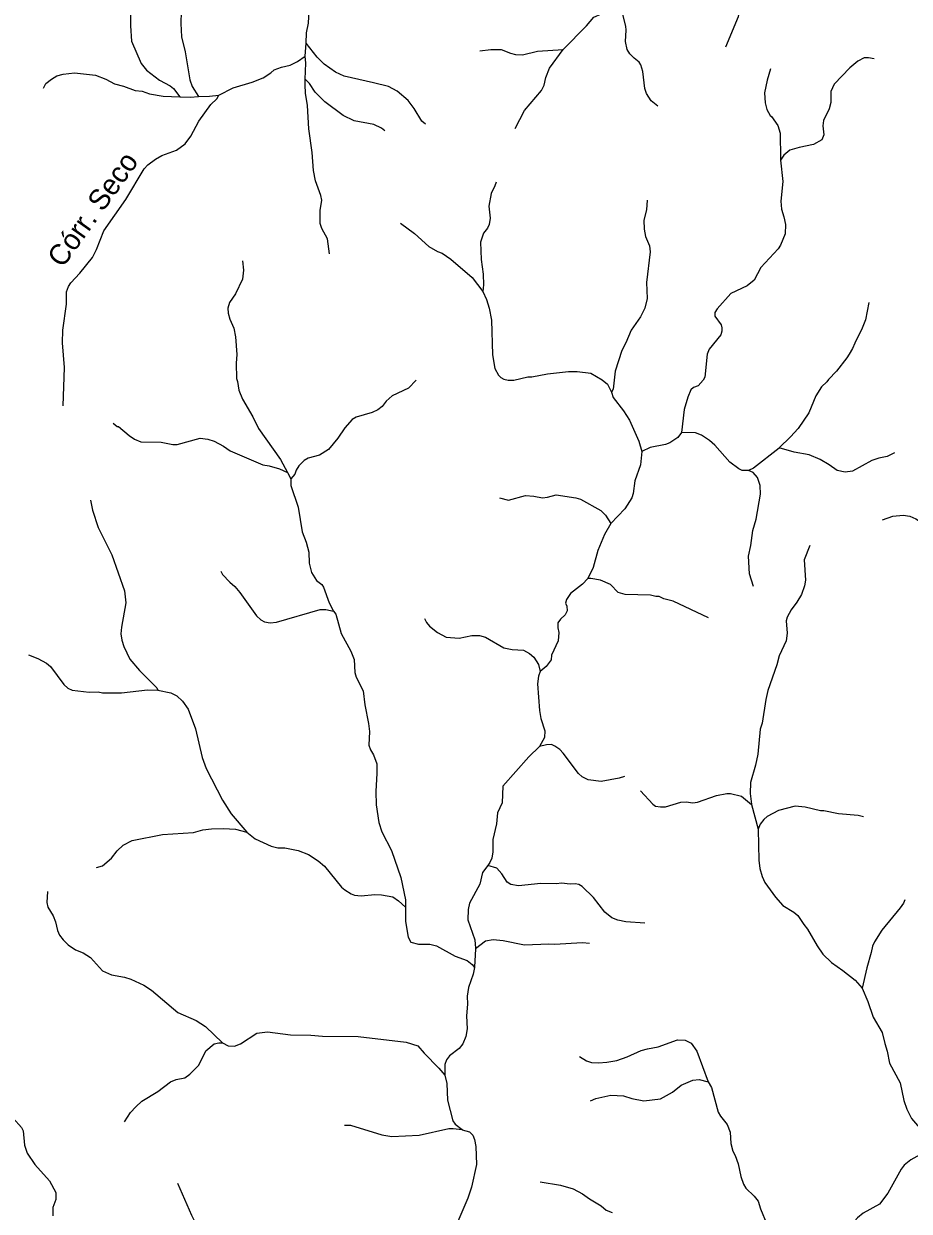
# Model space of a CAD drawing. Extents: x 500 to 555.2, y 9115.7 to 9171.
# Drawn here: x 506.57 to 513.43, y 9152.3 to 9161.51 of the extents above; entities that cross this region are included whole.
import ezdxf
from ezdxf.enums import TextEntityAlignment as Align

# ---------------------------------------------------------------- set-up
doc = ezdxf.new("R2010")
doc.units = 0
doc.header["$LTSCALE"] = 0.064
doc.layers.add('61', color=7, linetype='Continuous')
doc.layers.add('7', color=7, linetype='Continuous', lineweight=25)

msp = doc.modelspace()

# ---------------------------------------------------------------- linework, layer by layer
at = {"layer": '7'}
for p, q in [((508.747, 9161.2588), (508.7554, 9161.3589)), ((508.6097, 9158.0285), (508.6356, 9157.9796)), ((512.2057, 9155.4545), (512.2566, 9155.2643)), ((509.8286, 9153.3552), (509.8445, 9153.2913))]:
    msp.add_line(p, q, dxfattribs=at)
for points in [[(512.0079, 9161.3296), (512.1062, 9161.5663), (512.126, 9161.6638), (512.1276, 9161.7213), (512.1381, 9161.7481), (512.1532, 9161.7679), (512.1793, 9161.7797), (512.1942, 9161.7833), (512.2145, 9161.7826), (512.2757, 9161.753), (512.3157, 9161.743), (512.3493, 9161.7422), (512.3718, 9161.7497), (512.4665, 9161.8121), (512.5762, 9161.8589), (512.6381, 9161.8973), (512.6862, 9161.9426), (512.7107, 9162.0084), (512.7249, 9162.0852), (512.7809, 9162.164), (512.783, 9162.1652)], [(508.7554, 9161.3589), (508.757, 9161.4388), (508.773, 9161.5128), (508.7789, 9161.6115), (508.811, 9161.74), (508.8226, 9161.8187), (508.8257, 9161.8802)], [(507.3953, 9161.7929), (507.3925, 9161.4936), (507.4008, 9161.3752), (507.4757, 9161.2012), (507.5161, 9161.1489), (507.6167, 9161.0714), (507.7005, 9161.0283), (507.7258, 9161.0061), (507.776, 9160.9435)], [(507.7474, 9161.7496), (507.7531, 9161.7242), (507.7665, 9161.702), (507.7861, 9161.6036), (507.7828, 9161.51), (507.7879, 9161.4067), (507.8172, 9161.2919), (507.8535, 9161.0755), (507.8716, 9161.023), (507.9189, 9160.9438)], [(510.747, 9161.3091), (510.9278, 9161.4926), (510.985, 9161.5609), (511.1032, 9161.6127), (511.1848, 9161.6706)], [(511.4812, 9160.87), (511.4289, 9160.9118), (511.3927, 9160.9683), (511.3782, 9161.0083), (511.3652, 9161.1383), (511.3475, 9161.1897), (511.3353, 9161.2116), (511.2969, 9161.2423), (511.2628, 9161.2764), (511.2427, 9161.3105), (511.2292, 9161.3714), (511.2355, 9161.4593), (511.2323, 9161.4895), (511.1848, 9161.6706)], [(509.6788, 9160.7296), (509.6514, 9160.7542), (509.5905, 9160.8523), (509.5442, 9160.9147), (509.4587, 9160.9856), (509.3915, 9161.0215), (509.276, 9161.0511), (509.0482, 9161.1017), (508.9831, 9161.1338), (508.8938, 9161.1963), (508.8405, 9161.2506), (508.7554, 9161.3589)], [(510.0994, 9161.2982), (510.1853, 9161.3083), (510.267, 9161.31), (510.3381, 9161.2802), (510.3775, 9161.2705), (510.4319, 9161.269), (510.5469, 9161.2968), (510.747, 9161.3091)], [(510.3747, 9160.6963), (510.4469, 9160.8354), (510.5787, 9160.9906), (510.5989, 9161.0323), (510.6125, 9161.0924), (510.6407, 9161.1639), (510.7468, 9161.3089), (510.747, 9161.3091)], [(508.0787, 9160.9562), (508.188, 9161.0114), (508.3351, 9161.0555), (508.4218, 9161.0907), (508.48, 9161.128), (508.5069, 9161.1519), (508.5627, 9161.1724), (508.6303, 9161.1881), (508.6862, 9161.2161), (508.747, 9161.2588)], [(508.7475, 9161.0796), (508.7522, 9161.2045), (508.747, 9161.2588)], [(513.1563, 9161.2363), (513.1135, 9161.2459), (513.0801, 9161.2444), (513.0314, 9161.2188), (512.969, 9161.1685), (512.8468, 9161.0414), (512.8205, 9160.9842), (512.8202, 9160.8983), (512.8087, 9160.8492), (512.7648, 9160.7578), (512.758, 9160.7174), (512.766, 9160.6484), (512.751, 9160.608), (512.6878, 9160.5721), (512.5762, 9160.5502), (512.5041, 9160.5277), (512.4562, 9160.4913), (512.4312, 9160.4524)], [(506.7188, 9161.0104), (506.738, 9161.0453), (506.7796, 9161.0793), (506.8234, 9161.1049), (506.8713, 9161.1195), (506.9582, 9161.128), (507.1218, 9161.1098), (507.2027, 9161.0792), (507.2684, 9161.0433), (507.3378, 9161.0263), (507.4283, 9160.9924), (507.4832, 9160.9861), (507.5408, 9160.967), (507.6467, 9160.9475), (507.776, 9160.9435)], [(508.9353, 9159.7257), (508.9195, 9159.8403), (508.8751, 9159.9212), (508.8622, 9159.9606), (508.864, 9160.0623), (508.8753, 9160.1416), (508.8683, 9160.1774), (508.8276, 9160.292), (508.8115, 9160.3704), (508.8, 9160.5106), (508.7754, 9160.6936), (508.764, 9160.8763), (508.7491, 9160.9711), (508.7458, 9161.0354), (508.7475, 9161.0796)], [(509.3647, 9160.6801), (509.3387, 9160.6991), (509.2784, 9160.7289), (509.1277, 9160.7561), (509.0421, 9160.7986), (508.9002, 9160.9046), (508.8237, 9160.9794), (508.7792, 9161.0465), (508.7475, 9161.0796)], [(512.3546, 9161.1597), (512.3271, 9161.0709), (512.3072, 9160.9724), (512.3132, 9160.8968), (512.3258, 9160.844), (512.3498, 9160.7979), (512.3611, 9160.791), (512.4103, 9160.7206), (512.428, 9160.6601), (512.43, 9160.4632), (512.4312, 9160.4524)], [(506.8709, 9158.5462), (506.8808, 9158.8446), (506.866, 9159.0349), (506.8677, 9159.1339), (506.8971, 9159.3341), (506.897, 9159.4305), (506.9119, 9159.4712), (506.93, 9159.4991), (507.0008, 9159.575), (507.0988, 9159.696), (507.1298, 9159.7578), (507.1856, 9159.9021), (507.3577, 9160.1467), (507.4979, 9160.3836), (507.5265, 9160.4142), (507.5858, 9160.4592), (507.6348, 9160.487), (507.7484, 9160.5293), (507.8165, 9160.5778), (507.8609, 9160.6382), (507.923, 9160.7534), (508.015, 9160.8827), (508.0614, 9160.9259), (508.0787, 9160.9562)], [(507.776, 9160.9435), (507.8554, 9160.941), (507.9189, 9160.9438)], [(507.9189, 9160.9438), (508.0051, 9160.9476), (508.0777, 9160.9557), (508.0787, 9160.9562)], [(512.4312, 9160.4524), (512.4496, 9160.2849), (512.4333, 9160.1324), (512.4397, 9160.0716), (512.4577, 9160.0125), (512.4685, 9159.9514), (512.4673, 9159.8809), (512.4313, 9159.7928), (512.4127, 9159.7645), (512.2783, 9159.6201), (512.2279, 9159.5206), (512.1713, 9159.4781), (512.0472, 9159.4163), (511.94, 9159.2995), (511.9225, 9159.2702), (511.9218, 9159.2429), (511.9704, 9159.175), (511.9763, 9159.1504), (511.9763, 9159.1247), (511.9686, 9159.0965), (511.8781, 9158.9854), (511.8626, 9158.9468), (511.8443, 9158.7699), (511.8317, 9158.7456), (511.7938, 9158.7024), (511.7579, 9158.6889), (511.7351, 9158.6696), (511.7119, 9158.6131), (511.6854, 9158.5181), (511.6647, 9158.3397)], [(510.2261, 9160.2811), (510.2177, 9160.2518), (510.1877, 9160.1929), (510.1712, 9160.094), (510.1809, 9160.0016), (510.1733, 9159.952), (510.1606, 9159.9229), (510.1303, 9159.8861), (510.1065, 9159.8143), (510.1121, 9159.6819), (510.1268, 9159.567), (510.1299, 9159.4844), (510.1231, 9159.4331)], [(511.398, 9160.14), (511.3913, 9160.0671), (511.372, 9159.9869), (511.3735, 9159.9161), (511.3848, 9159.8589), (511.4158, 9159.7873), (511.4211, 9159.7411), (511.3932, 9159.502), (511.3965, 9159.3776), (511.3798, 9159.3034), (511.3462, 9159.2366), (511.2729, 9159.1321), (511.2321, 9159.0344), (511.2011, 9158.9753), (511.1505, 9158.8151), (511.1339, 9158.6766), (511.1199, 9158.6532)], [(509.4847, 9159.9635), (509.5954, 9159.8829), (509.7054, 9159.7829), (509.7737, 9159.7429), (509.8081, 9159.7304), (509.8754, 9159.6831), (510.0408, 9159.5409), (510.1231, 9159.4331)], [(508.2611, 9159.6706), (508.2684, 9159.5992), (508.2613, 9159.529), (508.208, 9159.416), (508.1603, 9159.3465), (508.1487, 9159.3039), (508.1503, 9159.2651), (508.1617, 9159.2192), (508.1947, 9159.1491), (508.2062, 9159.0802), (508.2175, 9158.9437), (508.2111, 9158.8781), (508.2143, 9158.7574), (508.2224, 9158.7355), (508.2324, 9158.6676), (508.2619, 9158.5969), (508.3419, 9158.4614), (508.3856, 9158.371), (508.5554, 9158.1311), (508.6097, 9158.0285)], [(510.1231, 9159.4331), (510.1513, 9159.3707), (510.1728, 9159.3033), (510.1923, 9159.2095), (510.1991, 9158.9424), (510.2168, 9158.8364), (510.2458, 9158.7853), (510.2637, 9158.7653), (510.2866, 9158.7526), (510.3189, 9158.7449), (510.3642, 9158.7446), (510.4732, 9158.7705), (510.5041, 9158.7709), (510.6255, 9158.7938), (510.788, 9158.8117), (510.8545, 9158.8134), (510.9614, 9158.7996), (511.0482, 9158.7482), (511.0894, 9158.7133), (511.1199, 9158.6532)], [(513.1147, 9159.3485), (513.0886, 9159.2135), (513.0638, 9159.148), (513.0069, 9159.0325), (512.9886, 9158.9904), (512.9633, 9158.9478), (512.9441, 9158.9192), (512.865, 9158.8153), (512.8019, 9158.7505), (512.7909, 9158.7319), (512.7495, 9158.6949), (512.7051, 9158.6242), (512.6499, 9158.4925), (512.5672, 9158.3702), (512.5092, 9158.3056), (512.4218, 9158.2211)], [(509.6071, 9158.7451), (509.5482, 9158.6826), (509.4206, 9158.6241), (509.3734, 9158.5817), (509.3439, 9158.5424), (509.3092, 9158.515), (509.2673, 9158.4953), (509.1421, 9158.4578), (509.1118, 9158.4401), (509.0535, 9158.3747), (509.0003, 9158.2951), (508.927, 9158.2074), (508.8583, 9158.1644), (508.7702, 9158.1414), (508.7393, 9158.1229), (508.6982, 9158.0802), (508.677, 9158.0475), (508.6659, 9158.0157), (508.6356, 9157.9796)], [(511.1199, 9158.6532), (511.133, 9158.6109), (511.2138, 9158.5069), (511.2596, 9158.4359), (511.3336, 9158.272), (511.3564, 9158.1912)], [(507.2579, 9158.4111), (507.2907, 9158.3869), (507.2994, 9158.3864), (507.3822, 9158.3153), (507.4232, 9158.2873), (507.4724, 9158.2659), (507.6309, 9158.2638), (507.7222, 9158.2476), (507.7544, 9158.2476), (507.9334, 9158.295), (507.9933, 9158.2872), (508.042, 9158.2721), (508.1126, 9158.2328), (508.1645, 9158.1962), (508.4189, 9158.0896), (508.4669, 9158.0819), (508.5489, 9158.0589), (508.6097, 9158.0285)], [(511.6647, 9158.3397), (511.6645, 9158.3383), (511.634, 9158.3011), (511.572, 9158.2583), (511.5394, 9158.2456), (511.4213, 9158.2241), (511.3564, 9158.1912)], [(512.1836, 9158.0439), (512.1346, 9158.0455), (512.1074, 9158.0578), (512.0391, 9158.1103), (511.9225, 9158.2415), (511.8803, 9158.2787), (511.8176, 9158.3189), (511.773, 9158.3378), (511.6647, 9158.3397)], [(511.3564, 9158.1912), (511.3451, 9158.0876), (511.3029, 9157.9648), (511.2881, 9157.8671), (511.2775, 9157.8329), (511.2242, 9157.7473), (511.1169, 9157.6334)], [(512.4218, 9158.2211), (512.4196, 9158.219), (512.2207, 9158.0632), (512.1836, 9158.0439)], [(513.3152, 9158.1823), (513.2576, 9158.1546), (513.1927, 9158.1414), (513.14, 9158.1237), (512.9891, 9158.0409), (512.9317, 9158.0311), (512.8696, 9158.046), (512.8092, 9158.0897), (512.739, 9158.1306), (512.6519, 9158.1669), (512.5381, 9158.187), (512.4218, 9158.2211)], [(512.2223, 9157.1443), (512.1901, 9157.2426), (512.1822, 9157.3815), (512.2, 9157.4641), (512.2152, 9157.5795), (512.2412, 9157.667), (512.2756, 9157.861), (512.2721, 9157.9274), (512.2535, 9157.99), (512.2187, 9158.0289), (512.1836, 9158.0439)], [(508.6356, 9157.9796), (508.6367, 9157.9288), (508.6927, 9157.7602), (508.7226, 9157.5692), (508.7539, 9157.4897), (508.775, 9157.4117), (508.7788, 9157.3275), (508.7957, 9157.2532), (508.8349, 9157.1916), (508.8764, 9157.1604), (508.8887, 9157.1398), (508.9325, 9157.018), (508.9675, 9156.9538)], [(510.2532, 9157.8328), (510.3237, 9157.8146), (510.4538, 9157.8505), (510.5194, 9157.8459), (510.5873, 9157.8328), (510.6255, 9157.8375), (510.6935, 9157.8572), (510.8434, 9157.8339), (510.8809, 9157.8213), (511.0372, 9157.734), (511.0749, 9157.6996), (511.1169, 9157.6334)], [(507.0835, 9157.8138), (507.099, 9157.7385), (507.1426, 9157.6017), (507.2481, 9157.3914), (507.3466, 9157.1118), (507.3579, 9157.0199), (507.3222, 9156.8288), (507.3187, 9156.7786), (507.3253, 9156.7287), (507.3414, 9156.6801), (507.3882, 9156.5814), (507.4618, 9156.4938), (507.5966, 9156.3607), (507.6061, 9156.3403)], [(513.2219, 9157.6625), (513.3005, 9157.6901), (513.3818, 9157.6997), (513.4324, 9157.6908), (513.4791, 9157.6704), (513.5297, 9157.639), (513.5786, 9157.6226), (513.6278, 9157.6178), (513.7087, 9157.6308), (513.799, 9157.632), (513.9171, 9157.6058), (514.01, 9157.5689), (514.1363, 9157.5076), (514.279, 9157.4541), (514.4025, 9157.3858), (514.4503, 9157.3506)], [(511.1169, 9157.6334), (511.0667, 9157.5487), (511.0148, 9157.4256), (510.9795, 9157.2923), (510.9384, 9157.207)], [(512.658, 9157.4625), (512.6153, 9157.352), (512.6249, 9157.1951), (512.6182, 9157.1513), (512.5935, 9157.0825), (512.5586, 9157.0228), (512.5132, 9156.9644), (512.4828, 9156.907), (512.4757, 9156.8799), (512.4824, 9156.7834), (512.476, 9156.7235), (512.4202, 9156.6079), (512.4037, 9156.5391), (512.333, 9156.3377), (512.3164, 9156.2681), (512.2885, 9156.0851), (512.2724, 9156.0391), (512.2543, 9155.8463), (512.2373, 9155.7586), (512.1988, 9155.6245), (512.1954, 9155.5401), (512.2051, 9155.4568), (512.2057, 9155.4545)], [(508.0927, 9157.2633), (508.107, 9157.2377), (508.1628, 9157.1789), (508.2015, 9157.1465), (508.2417, 9157.0997), (508.3687, 9156.9171), (508.4034, 9156.8875), (508.4304, 9156.8726), (508.4751, 9156.8633), (508.5249, 9156.8699), (508.8638, 9156.9665), (508.9076, 9156.9681), (508.9675, 9156.9538)], [(510.9384, 9157.207), (510.8959, 9157.1642), (510.8027, 9157.0911), (510.7715, 9157.0452), (510.765, 9157.0162), (510.7746, 9156.9916), (510.7776, 9156.9578), (510.7612, 9156.9268), (510.726, 9156.893), (510.706, 9156.8624), (510.7043, 9156.8245), (510.7123, 9156.7877), (510.7075, 9156.7245), (510.6568, 9156.6121), (510.6545, 9156.5756), (510.6144, 9156.5242), (510.5691, 9156.4859)], [(511.8718, 9156.9011), (511.5994, 9157.0315), (511.5273, 9157.0509), (511.4896, 9157.0677), (511.4653, 9157.0668), (511.4226, 9157.0779), (511.2265, 9157.083), (511.1721, 9157.0995), (511.1127, 9157.1617), (511.0356, 9157.1944), (510.962, 9157.2076), (510.9384, 9157.207)], [(508.9675, 9156.9538), (508.9857, 9156.9315), (509.025, 9156.7797), (509.101, 9156.6448), (509.1277, 9156.5784), (509.1314, 9156.4794), (509.1428, 9156.4433), (509.1967, 9156.335), (509.2081, 9156.2283), (509.238, 9156.0842), (509.2442, 9156.0207), (509.2415, 9155.9147), (509.2543, 9155.8793), (509.2767, 9155.8402), (509.3018, 9155.7701), (509.3034, 9155.6985), (509.2936, 9155.5558), (509.2969, 9155.4525), (509.3184, 9155.3141), (509.3406, 9155.244), (509.4152, 9155.0976), (509.489, 9154.8876), (509.5247, 9154.716), (509.5242, 9154.6587)], [(509.6707, 9156.8974), (509.6865, 9156.8661), (509.7108, 9156.8367), (509.7731, 9156.789), (509.8388, 9156.7515), (509.9412, 9156.7451), (510.0396, 9156.7665), (510.0979, 9156.7662), (510.1439, 9156.7513), (510.2854, 9156.6708), (510.3512, 9156.6563), (510.438, 9156.651), (510.486, 9156.6253), (510.5188, 9156.5973), (510.5545, 9156.5392), (510.5691, 9156.4859)], [(506.6038, 9156.6152), (506.6752, 9156.5878), (506.7413, 9156.5499), (506.7731, 9156.5245), (506.8765, 9156.3853), (506.9086, 9156.358), (506.9401, 9156.3411), (507.072, 9156.3269), (507.1421, 9156.3284), (507.1749, 9156.3219), (507.3233, 9156.3219), (507.5248, 9156.3431), (507.6061, 9156.3403)], [(510.5691, 9156.4859), (510.5544, 9156.4493), (510.5469, 9156.3901), (510.5633, 9156.1835), (510.5738, 9156.1223), (510.604, 9156.0273), (510.6025, 9155.9748), (510.5632, 9155.9035)], [(507.6061, 9156.3403), (507.7052, 9156.3204), (507.7517, 9156.2971), (507.7959, 9156.2562), (507.8402, 9156.1939), (507.8956, 9156.0412), (507.9474, 9155.8185), (507.9787, 9155.7339), (508.1057, 9155.4893), (508.1737, 9155.3831), (508.2946, 9155.2416)], [(511.2225, 9155.6718), (511.1797, 9155.6578), (511.0402, 9155.633), (510.941, 9155.646), (510.895, 9155.6704), (510.8645, 9155.6957), (510.7468, 9155.8527), (510.7206, 9155.8805), (510.6829, 9155.908), (510.6549, 9155.9198), (510.618, 9155.9181), (510.5632, 9155.9035)], [(510.5632, 9155.9035), (510.48, 9155.8253), (510.2781, 9155.5968), (510.2749, 9155.4678), (510.2368, 9155.3897), (510.2307, 9155.3042), (510.2002, 9155.1826), (510.2023, 9155.0872), (510.194, 9155.0393), (510.1788, 9155.0041), (510.1631, 9154.9807)], [(511.3462, 9155.5603), (511.4415, 9155.4566), (511.4616, 9155.4431), (511.5001, 9155.4363), (511.5402, 9155.4377), (511.659, 9155.4738), (511.6989, 9155.4754), (511.752, 9155.469), (511.7868, 9155.4739), (511.9346, 9155.5246), (512.016, 9155.541), (512.0422, 9155.541), (512.1274, 9155.5199), (512.2057, 9155.4545)], [(513.0747, 9155.3592), (513.0316, 9155.3691), (512.8803, 9155.3837), (512.7672, 9155.4049), (512.7415, 9155.405), (512.6229, 9155.4345), (512.5452, 9155.4426), (512.4162, 9155.408), (512.3287, 9155.361), (512.3014, 9155.3387), (512.2739, 9155.3034), (512.2566, 9155.2643)], [(507.1287, 9154.9656), (507.1748, 9154.9805), (507.2465, 9155.0376), (507.2901, 9155.0959), (507.3368, 9155.1392), (507.4061, 9155.1763), (507.6408, 9155.2228), (507.882, 9155.2387), (507.9525, 9155.2575), (508.0202, 9155.2673), (508.1141, 9155.2688), (508.2062, 9155.2623), (508.2946, 9155.2416)], [(508.2946, 9155.2416), (508.3593, 9155.1899), (508.4827, 9155.1313), (508.5358, 9155.1196), (508.5897, 9155.1193), (508.6932, 9155.0982), (508.7733, 9155.0662), (508.8485, 9155.0182), (508.8961, 9154.9773), (509.0295, 9154.8144), (509.0533, 9154.7921), (509.1021, 9154.761), (509.1297, 9154.7522), (509.1806, 9154.7472), (509.2856, 9154.757), (509.3381, 9154.7555), (509.427, 9154.7392), (509.4713, 9154.7089), (509.5242, 9154.6587)], [(512.2566, 9155.2643), (512.2572, 9155.2619), (512.2626, 9155.0221), (512.2709, 9154.9598), (512.2883, 9154.8963), (512.3083, 9154.8496), (512.3914, 9154.7361), (512.4495, 9154.6719), (512.5331, 9154.6208), (512.5642, 9154.593), (512.6107, 9154.5236), (512.6414, 9154.488), (512.7156, 9154.3596), (512.76, 9154.2941), (512.8257, 9154.2301), (512.9148, 9154.1685), (513.0093, 9154.0921), (513.0649, 9154.0301)], [(510.1631, 9154.9807), (510.1219, 9154.9269), (510.1, 9154.8377), (510.0217, 9154.6908), (510.0102, 9154.6417), (510.0072, 9154.561), (510.0629, 9154.406), (510.068, 9154.34), (510.0677, 9154.3346)], [(511.3782, 9154.5341), (511.2319, 9154.5456), (511.1696, 9154.5587), (511.1234, 9154.5761), (511.0693, 9154.6201), (510.9814, 9154.7324), (510.8935, 9154.8185), (510.867, 9154.8334), (510.8387, 9154.8406), (510.8, 9154.8375), (510.7338, 9154.8439), (510.6955, 9154.8391), (510.5733, 9154.8424), (510.3998, 9154.8245), (510.3408, 9154.834), (510.3134, 9154.8515), (510.2712, 9154.9178), (510.232, 9154.9607), (510.1631, 9154.9807)], [(506.7504, 9154.781), (506.7445, 9154.6956), (506.7532, 9154.6581), (506.7946, 9154.5911), (506.8118, 9154.5438), (506.8266, 9154.4788), (506.8437, 9154.441), (506.87, 9154.4055), (506.9092, 9154.366), (506.9666, 9154.3279), (507.0273, 9154.304), (507.0823, 9154.2696), (507.1769, 9154.1645), (507.2453, 9154.1342), (507.3455, 9154.1155), (507.3947, 9154.1007), (507.4953, 9154.0536), (507.5565, 9154.0156), (507.76, 9153.8412), (507.9021, 9153.7788), (507.9739, 9153.7325), (508.1065, 9153.6056)], [(509.5242, 9154.6587), (509.5233, 9154.5471), (509.5462, 9154.4264), (509.5663, 9154.3881), (509.625, 9154.3717), (509.7135, 9154.3715), (509.7659, 9154.3583), (509.9097, 9154.2784), (510.0022, 9154.2451), (510.0416, 9154.2152), (510.0587, 9154.1904)], [(513.3946, 9154.7152), (513.3853, 9154.691), (513.3587, 9154.6543), (513.2155, 9154.4815), (513.1582, 9154.3896), (513.1431, 9154.3556), (513.1348, 9154.3071), (513.0991, 9154.1895), (513.0649, 9154.0301)], [(510.9503, 9154.3778), (510.8974, 9154.3815), (510.6789, 9154.3686), (510.6342, 9154.3717), (510.4458, 9154.3651), (510.2822, 9154.3965), (510.2043, 9154.4059), (510.1454, 9154.3939), (510.0677, 9154.3346)], [(510.0677, 9154.3346), (510.0593, 9154.194), (510.0587, 9154.1904)], [(510.0587, 9154.1904), (510.0498, 9154.1396), (510.0138, 9154.0353), (510.0023, 9153.9697), (510.0053, 9153.9074), (509.9974, 9153.817), (510.0016, 9153.7159), (509.9919, 9153.6566), (509.9677, 9153.5991), (509.9405, 9153.5621), (509.8659, 9153.5059), (509.8416, 9153.4742), (509.8299, 9153.4379), (509.8286, 9153.3552)], [(513.0649, 9154.0301), (513.1078, 9153.9285), (513.15, 9153.8051), (513.2194, 9153.6862), (513.2397, 9153.602), (513.2582, 9153.5432), (513.2763, 9153.4497), (513.3572, 9153.2966), (513.3869, 9153.16), (513.411, 9153.0932), (513.4473, 9153.0211), (513.5382, 9152.9123), (513.5654, 9152.8629), (513.5715, 9152.8415), (513.5793, 9152.7762)], [(508.1065, 9153.6056), (508.1512, 9153.5834), (508.2, 9153.58), (508.2467, 9153.5982), (508.3714, 9153.6822), (508.4539, 9153.6924), (508.6336, 9153.6679), (508.7917, 9153.6662), (508.8821, 9153.6581), (509.1573, 9153.6563), (509.5292, 9153.6121), (509.6195, 9153.5831), (509.6681, 9153.5264), (509.784, 9153.4103), (509.8286, 9153.3552)], [(510.874, 9153.5014), (510.9267, 9153.4665), (510.9662, 9153.4548), (511.021, 9153.4513), (511.0854, 9153.4564), (511.1623, 9153.4707), (511.2429, 9153.4992), (511.3517, 9153.5469), (511.3992, 9153.561), (511.4817, 9153.5745), (511.6326, 9153.6301), (511.6911, 9153.6286), (511.7374, 9153.6052), (511.7819, 9153.5415), (511.8706, 9153.304)], [(507.3476, 9152.9941), (507.3934, 9153.0652), (507.4332, 9153.1114), (507.48, 9153.1536), (507.6041, 9153.23), (507.7043, 9153.303), (507.7472, 9153.3215), (507.8134, 9153.3364), (507.8534, 9153.3628), (507.9223, 9153.4334), (507.9778, 9153.5442), (508.0428, 9153.599), (508.0782, 9153.607), (508.1065, 9153.6056)], [(506.4127, 9153.5033), (506.4231, 9153.4165), (506.415, 9153.33), (506.4147, 9153.2405), (506.4503, 9153.0881), (506.4835, 9153.0222), (506.5471, 9152.9499), (506.5606, 9152.9245), (506.5705, 9152.813), (506.5924, 9152.7504), (506.6512, 9152.6641), (506.7656, 9152.5376), (506.8133, 9152.4466), (506.8134, 9152.3906), (506.7906, 9152.3296), (506.7906, 9152.2645)], [(509.8445, 9153.2913), (509.8496, 9153.1622), (509.8904, 9153.0025), (509.9107, 9152.9749), (509.9639, 9152.9335)], [(510.9574, 9153.1561), (510.9996, 9153.1741), (511.1149, 9153.202), (511.2133, 9153.1952), (511.2789, 9153.174), (511.3712, 9153.1582), (511.501, 9153.1736), (511.5944, 9153.223), (511.6617, 9153.2794), (511.7506, 9153.3183), (511.7993, 9153.3234), (511.8706, 9153.304)], [(511.8706, 9153.304), (511.8956, 9153.2607), (511.9482, 9153.07), (511.9653, 9153.0386), (512.0164, 9152.9724), (512.0412, 9152.9127), (512.046, 9152.8255), (512.0605, 9152.7672), (512.079, 9152.7323), (512.1017, 9152.6673), (512.123, 9152.5696), (512.1445, 9152.5099), (512.1634, 9152.4792), (512.2264, 9152.418), (512.2568, 9152.3783), (512.2762, 9152.3183), (512.3253, 9152.201)], [(509.0515, 9152.9675), (509.0994, 9152.9675), (509.3407, 9152.8943), (509.4183, 9152.8806), (509.6302, 9152.8919), (509.8606, 9152.9412), (509.8947, 9152.9427), (509.9639, 9152.9335)], [(509.9639, 9152.9335), (509.9647, 9152.9328), (510.0198, 9152.9154), (510.0453, 9152.8909), (510.0591, 9152.8563), (510.0694, 9152.8018), (510.0743, 9152.6634), (510.035, 9152.487), (510.0071, 9152.4011), (509.9307, 9152.2224)], [(513.5793, 9152.7762), (513.4408, 9152.7005), (513.3889, 9152.6569), (513.3655, 9152.6281), (513.2618, 9152.4415), (513.198, 9152.3568), (513.0717, 9152.2871), (513.027, 9152.2506), (512.9891, 9152.2068), (512.9701, 9152.1727), (512.9417, 9152.0866), (512.9372, 9151.9834), (512.9364, 9151.9792)], [(507.7567, 9152.5184), (507.8647, 9152.2709), (507.9128, 9152.177), (507.9475, 9152.1371), (508.0112, 9152.0852), (508.1093, 9152.0243), (508.2671, 9151.9122), (508.4186, 9151.709), (508.4439, 9151.6644), (508.457, 9151.5952), (508.475, 9151.5501)], [(510.569, 9152.5281), (510.726, 9152.5035), (510.8249, 9152.474), (510.8957, 9152.4369), (510.9499, 9152.3971), (511.0405, 9152.3425), (511.0805, 9152.308), (511.1257, 9152.29)]]:
    msp.add_lwpolyline(points, dxfattribs=at)

# ---------------------------------------------------------------- texts
at = {"layer": '61'}
msp.add_text('Córr. Seco', height=0.16, rotation=54.462, dxfattribs=at).set_placement((507.1644, 9160.0252), align=Align.CENTER)

doc.saveas('drawing.dxf')
